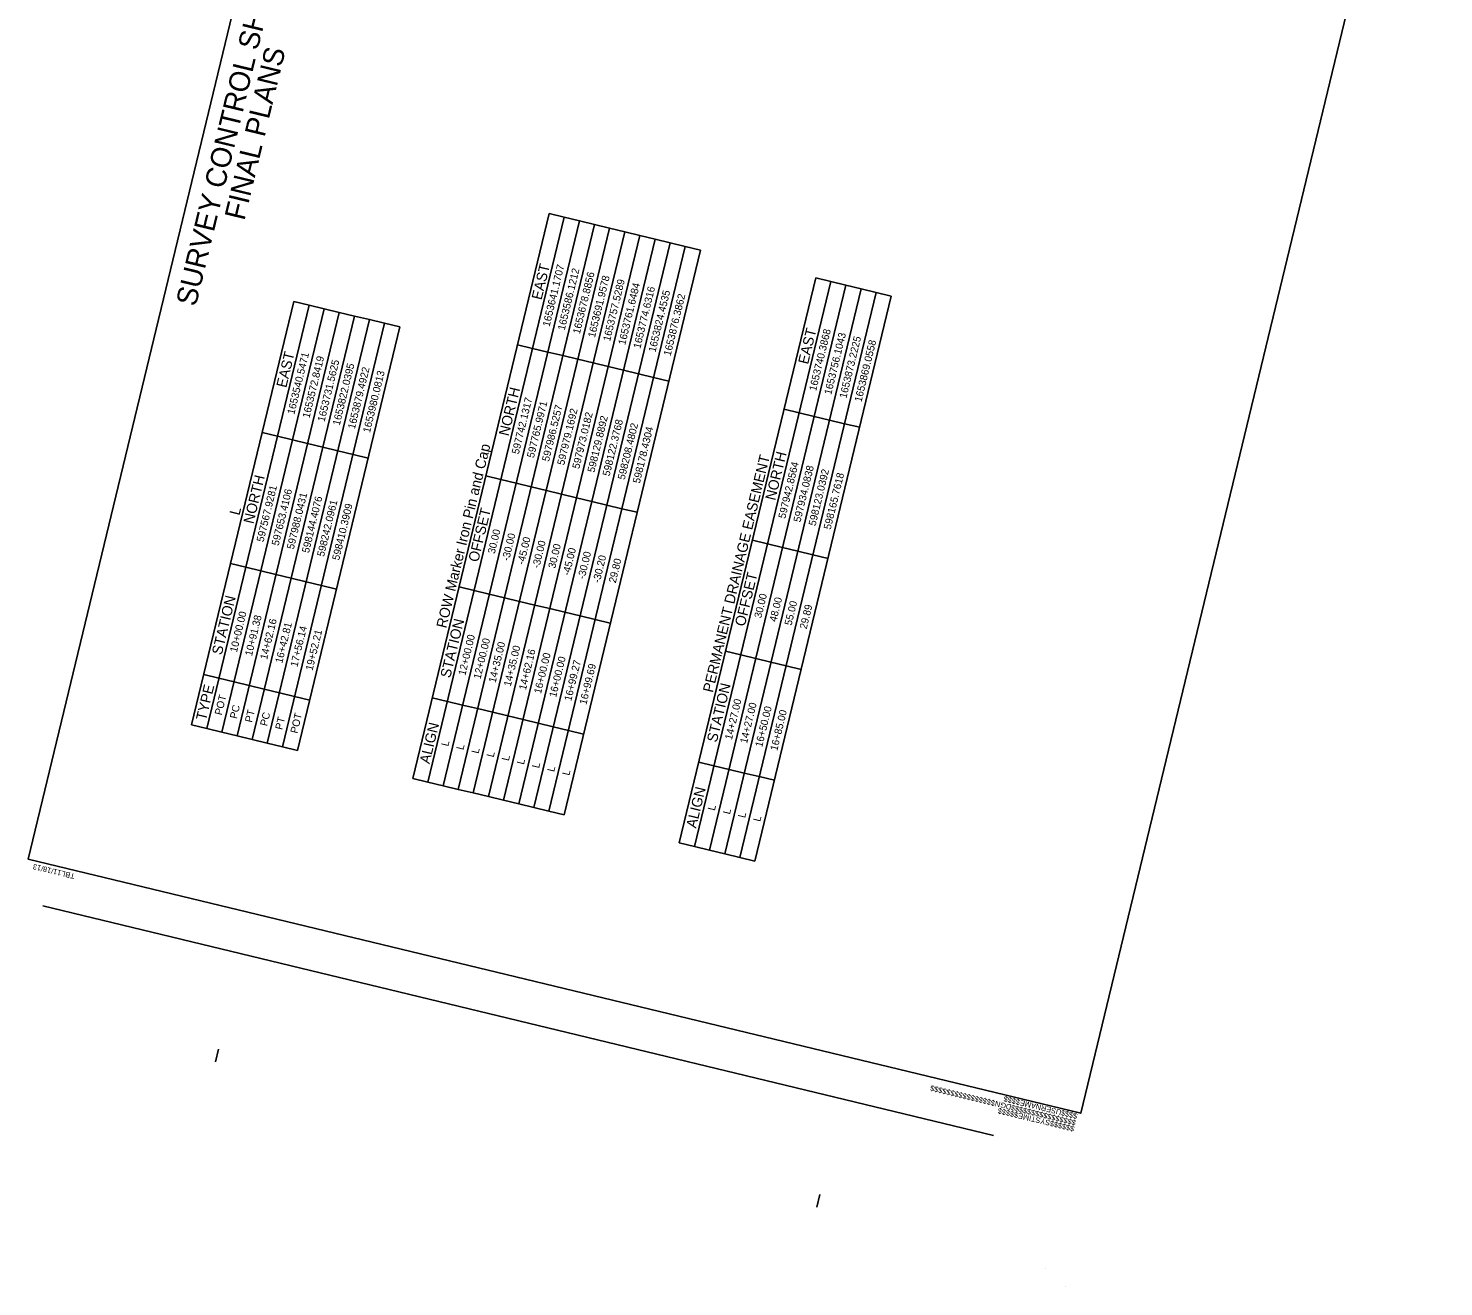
# Model space of a CAD drawing. Extents: x 1649669 to 1659218, y 594717 to 607900.
# Drawn here: x 1649669 to 1659218, y 594717 to 603207 of the extents above; entities that cross this region are included whole.
import ezdxf

# ---------------------------------------------------------------- set-up
doc = ezdxf.new("R2010")
doc.units = 0
for name, color, linetype in [('CTL Sheet Border CELL', 7, 'Continuous'), ('CTL Sheet Notes CELL', 7, 'Continuous'), ('CTL Sheet Table Cell', 7, 'Continuous'), ('CTL Sheet Text', 7, 'Continuous'), ('Sheet Cutting Line CELL', 7, 'Continuous')]:
    doc.layers.add(name, color=color, linetype=linetype)

msp = doc.modelspace()

# ---------------------------------------------------------------- linework, layer by layer
at = {"layer": 'CTL Sheet Border CELL'}
for p, q in [((1650930.7, 596233.5), (1650951.1, 596318)), ((1656768.8, 595886.6), (1656768.8, 595886.6)), ((1656768.8, 595886.6), (1656768.8, 595886.6)), ((1656768.8, 595886.6), (1656768.8, 595886.6)), ((1656768.8, 595886.6), (1656768.8, 595886.6)), ((1656768.8, 595886.6), (1656768.8, 595886.6)), ((1656768.8, 595886.6), (1656768.8, 595886.6)), ((1656768.8, 595886.6), (1656768.8, 595886.6)), ((1656768.8, 595886.6), (1656768.8, 595886.6)), ((1656768.8, 595886.6), (1656768.8, 595886.6)), ((1656768.8, 595886.6), (1656768.8, 595886.6)), ((1656768.8, 595886.6), (1656768.8, 595886.6)), ((1654988, 595253.9), (1655008.4, 595338.4)), ((1656534.7, 594841.1), (1656534.7, 594841.1)), ((1656665.2, 594716.6), (1656665.2, 594716.6))]:
    msp.add_line(p, q, dxfattribs=at)
msp.add_lwpolyline([(1652117.6, 607744.3), (1649668.6, 597600.9), (1656768.8, 595886.6), (1659217.9, 606030)], close=True, dxfattribs=at)
msp.add_lwpolyline([(1656830.1, 596140.2), (1656830.1, 596140.2)], dxfattribs=at)
msp.add_lwpolyline([(1656830.1, 596140.2), (1656830.1, 596140.2)], dxfattribs=at)
at = {"layer": 'CTL Sheet Table Cell'}
for p, q in [((1652262.5, 598146.1), (1653182.5, 601956.6)), ((1652364.6, 598121.4), (1653284.6, 601931.9)), ((1652466.7, 598096.8), (1653386.7, 601907.3)), ((1653182.5, 601956.6), (1653284.6, 601931.9)), ((1653284.6, 601931.9), (1653386.7, 601907.3)), ((1653386.7, 601907.3), (1653488.7, 601882.6)), ((1652568.7, 598072.1), (1653488.7, 601882.6)), ((1652670.8, 598047.5), (1653590.8, 601858)), ((1652772.9, 598022.8), (1653692.9, 601833.4)), ((1652874.9, 597998.2), (1653794.9, 601808.7)), ((1653488.7, 601882.6), (1653590.8, 601858)), ((1653590.8, 601858), (1653692.9, 601833.4)), ((1653692.9, 601833.4), (1653794.9, 601808.7)), ((1653794.9, 601808.7), (1653897, 601784.1)), ((1652977, 597973.6), (1653897, 601784.1)), ((1653079.1, 597948.9), (1653999.1, 601759.4)), ((1653181.1, 597924.3), (1654101.1, 601734.8)), ((1653283.2, 597899.6), (1654203.2, 601710.1)), ((1653897, 601784.1), (1653999.1, 601759.4)), ((1653999.1, 601759.4), (1654101.1, 601734.8)), ((1654101.1, 601734.8), (1654203.2, 601710.1)), ((1654060.8, 597711.9), (1654980.9, 601522.4)), ((1654980.9, 601522.4), (1655082.9, 601497.7)), ((1654162.9, 597687.2), (1655082.9, 601497.7)), ((1654265, 597662.6), (1655185, 601473.1)), ((1654367, 597637.9), (1655287.1, 601448.4)), ((1654469.1, 597613.3), (1655389.1, 601423.8)), ((1655082.9, 601497.7), (1655185, 601473.1)), ((1655185, 601473.1), (1655287.1, 601448.4)), ((1655287.1, 601448.4), (1655389.1, 601423.8)), ((1655389.1, 601423.8), (1655491.2, 601399.2)), ((1650770.4, 598506.3), (1651460.4, 601364.2)), ((1650872.5, 598481.7), (1651562.5, 601339.6)), ((1651460.4, 601364.2), (1651562.5, 601339.6)), ((1651562.5, 601339.6), (1651664.5, 601314.9)), ((1654571.2, 597588.6), (1655491.2, 601399.2)), ((1650974.5, 598457), (1651664.5, 601314.9)), ((1651076.6, 598432.4), (1651766.6, 601290.3)), ((1651178.7, 598407.8), (1651868.7, 601265.6)), ((1651280.7, 598383.1), (1651970.7, 601241)), ((1651664.5, 601314.9), (1651766.6, 601290.3)), ((1651766.6, 601290.3), (1651868.7, 601265.6)), ((1651868.7, 601265.6), (1651970.7, 601241)), ((1651970.7, 601241), (1652072.8, 601216.3)), ((1651382.8, 598358.5), (1652072.8, 601216.3)), ((1651484.9, 598333.8), (1652174.9, 601191.7)), ((1652072.8, 601216.3), (1652174.9, 601191.7)), ((1652969, 601072), (1653071, 601047.3)), ((1653071, 601047.3), (1653173.1, 601022.7)), ((1653173.1, 601022.7), (1653275.2, 600998.1)), ((1653275.2, 600998.1), (1653377.2, 600973.4)), ((1653377.2, 600973.4), (1653479.3, 600948.8)), ((1653479.3, 600948.8), (1653581.4, 600924.1)), ((1653581.4, 600924.1), (1653683.4, 600899.5)), ((1653683.4, 600899.5), (1653785.5, 600874.8)), ((1653785.5, 600874.8), (1653887.6, 600850.2)), ((1653887.6, 600850.2), (1653989.6, 600825.6)), ((1654767.3, 600637.8), (1654869.4, 600613.1)), ((1654869.4, 600613.1), (1654971.4, 600588.5)), ((1654971.4, 600588.5), (1655073.5, 600563.9)), ((1655073.5, 600563.9), (1655175.6, 600539.2)), ((1651246.8, 600479.6), (1651348.9, 600455)), ((1655175.6, 600539.2), (1655277.6, 600514.6)), ((1651348.9, 600455), (1651451, 600430.3)), ((1651451, 600430.3), (1651553, 600405.7)), ((1651553, 600405.7), (1651655.1, 600381)), ((1651655.1, 600381), (1651757.2, 600356.4)), ((1651757.2, 600356.4), (1651859.2, 600331.8)), ((1651859.2, 600331.8), (1651961.3, 600307.1)), ((1652755.4, 600187.4), (1652857.5, 600162.8)), ((1652857.5, 600162.8), (1652959.5, 600138.1)), ((1652959.5, 600138.1), (1653061.6, 600113.5)), ((1653061.6, 600113.5), (1653163.7, 600088.8)), ((1653163.7, 600088.8), (1653265.7, 600064.2)), ((1653265.7, 600064.2), (1653367.8, 600039.5)), ((1653367.8, 600039.5), (1653469.9, 600014.9)), ((1653469.9, 600014.9), (1653571.9, 599990.3)), ((1653571.9, 599990.3), (1653674, 599965.6)), ((1653674, 599965.6), (1653776.1, 599941)), ((1654553.7, 599753.2), (1654655.8, 599728.6)), ((1654655.8, 599728.6), (1654757.9, 599703.9)), ((1654757.9, 599703.9), (1654859.9, 599679.3)), ((1654859.9, 599679.3), (1654962, 599654.6)), ((1654962, 599654.6), (1655064.1, 599630)), ((1651033.3, 599595), (1651135.3, 599570.4)), ((1651135.3, 599570.4), (1651237.4, 599545.8)), ((1651237.4, 599545.8), (1651339.5, 599521.1)), ((1651339.5, 599521.1), (1651441.5, 599496.5)), ((1651441.5, 599496.5), (1651543.6, 599471.8)), ((1651543.6, 599471.8), (1651645.7, 599447.2)), ((1651645.7, 599447.2), (1651747.7, 599422.5)), ((1652574.7, 599438.9), (1652676.7, 599414.3)), ((1652676.7, 599414.3), (1652778.8, 599389.6)), ((1652778.8, 599389.6), (1652880.9, 599365)), ((1652880.9, 599365), (1652982.9, 599340.3)), ((1652982.9, 599340.3), (1653085, 599315.7)), ((1653085, 599315.7), (1653187.1, 599291.1)), ((1653187.1, 599291.1), (1653289.1, 599266.4)), ((1653289.1, 599266.4), (1653391.2, 599241.8)), ((1653391.2, 599241.8), (1653493.3, 599217.1)), ((1653493.3, 599217.1), (1653595.3, 599192.5)), ((1654373, 599004.7), (1654475.1, 598980.1)), ((1654475.1, 598980.1), (1654577.1, 598955.4)), ((1654577.1, 598955.4), (1654679.2, 598930.8)), ((1650852.5, 598846.5), (1650954.6, 598821.9)), ((1654679.2, 598930.8), (1654781.3, 598906.1)), ((1654781.3, 598906.1), (1654883.3, 598881.5)), ((1650954.6, 598821.9), (1651056.7, 598797.3)), ((1651056.7, 598797.3), (1651158.7, 598772.6)), ((1651158.7, 598772.6), (1651260.8, 598748)), ((1651260.8, 598748), (1651362.9, 598723.3)), ((1651362.9, 598723.3), (1651464.9, 598698.7)), ((1651464.9, 598698.7), (1651567, 598674)), ((1652394, 598690.4), (1652496, 598665.8)), ((1652496, 598665.8), (1652598.1, 598641.1)), ((1652598.1, 598641.1), (1652700.2, 598616.5)), ((1652700.2, 598616.5), (1652802.2, 598591.8)), ((1652802.2, 598591.8), (1652904.3, 598567.2)), ((1652904.3, 598567.2), (1653006.4, 598542.6)), ((1650770.4, 598506.3), (1650872.5, 598481.7)), ((1650872.5, 598481.7), (1650974.5, 598457)), ((1650974.5, 598457), (1651076.6, 598432.4)), ((1653006.4, 598542.6), (1653108.4, 598517.9)), ((1653108.4, 598517.9), (1653210.5, 598493.3)), ((1653210.5, 598493.3), (1653312.6, 598468.6)), ((1653312.6, 598468.6), (1653414.6, 598444)), ((1651076.6, 598432.4), (1651178.7, 598407.8)), ((1651178.7, 598407.8), (1651280.7, 598383.1)), ((1651280.7, 598383.1), (1651382.8, 598358.5)), ((1651382.8, 598358.5), (1651484.9, 598333.8)), ((1654192.3, 598256.2), (1654294.3, 598231.6)), ((1654294.3, 598231.6), (1654396.4, 598206.9)), ((1654396.4, 598206.9), (1654498.5, 598182.3)), ((1654498.5, 598182.3), (1654600.5, 598157.7)), ((1652262.5, 598146.1), (1652364.6, 598121.4)), ((1652364.6, 598121.4), (1652466.7, 598096.8)), ((1652466.7, 598096.8), (1652568.7, 598072.1)), ((1654600.5, 598157.7), (1654702.6, 598133)), ((1652568.7, 598072.1), (1652670.8, 598047.5)), ((1652670.8, 598047.5), (1652772.9, 598022.8)), ((1652772.9, 598022.8), (1652874.9, 597998.2)), ((1652874.9, 597998.2), (1652977, 597973.6)), ((1652977, 597973.6), (1653079.1, 597948.9)), ((1653079.1, 597948.9), (1653181.1, 597924.3)), ((1653181.1, 597924.3), (1653283.2, 597899.6)), ((1654060.8, 597711.9), (1654162.9, 597687.2)), ((1654162.9, 597687.2), (1654265, 597662.6)), ((1654265, 597662.6), (1654367, 597637.9)), ((1654367, 597637.9), (1654469.1, 597613.3)), ((1654469.1, 597613.3), (1654571.2, 597588.6))]:
    msp.add_line(p, q, dxfattribs=at)
at = {"layer": 'Sheet Cutting Line CELL'}
msp.add_line((1649765.8, 597285.3), (1656181.4, 595736.3), dxfattribs=at)

# ---------------------------------------------------------------- texts
at = {"layer": 'CTL Sheet Border CELL'}
for s, height, rotation, p in [('SURVEY CONTROL SHEET', 139.13, 76.42607, (1650798.4, 601324.6)), ('FINAL PLANS', 139.13, 76.42607, (1651126.1, 601904.5)), ('TBL11/18/13', 36.522, 166.42607, (1649985.4, 597502)), ('$$$$$$$$$$$$$$$$DGN$$$$$$$$$$$$$$$$', 36.522, 166.42607, (1656740.4, 595838.9)), ('$$$$USERNAME$$$$', 36.522, 166.42607, (1656751, 595883.3)), ('$$$$$$SYSTIME$$$$$', 36.522, 166.42607, (1656730.5, 595797.9))]:
    msp.add_text(s, height=height, rotation=rotation, dxfattribs=at).set_placement(p)
at = {"layer": 'CTL Sheet Notes CELL'}
for s, p in [('EAST', (1653130.9, 601370)), ('EAST', (1654929.3, 600935.8)), ('EAST', (1651408.8, 600777.6)), ('NORTH', (1652909.2, 600451.6)), ('ROW Marker Iron Pin and Cap', (1652488.2, 599155.3)), ('PERMANENT DRAINAGE EASEMENT', (1654286.5, 598721.1)), ('NORTH', (1654707.5, 600017.4)), ('NORTH', (1651187.1, 599859.3)), ('L', (1651093, 599916.9)), ('OFFSET', (1652703.9, 599601.3)), ('OFFSET', (1654502.2, 599167.2)), ('STATION', (1650973.6, 598975.2)), ('STATION', (1652515, 598819.1)), ('TYPE', (1650866.6, 598532.1)), ('STATION', (1654313.4, 598384.9)), ('ALIGN', (1652375.3, 598240.2)), ('ALIGN', (1654173.6, 597806))]:
    msp.add_text(s, height=70, rotation=76.42607, dxfattribs=at).set_placement(p)
at = {"layer": 'CTL Sheet Text'}
for s, p in [('1653641.1707', (1653185.2, 601190.2)), ('1653586.1212', (1653287.3, 601165.5)), ('1653678.8856', (1653389.4, 601140.9)), ('1653691.9578', (1653491.4, 601116.2)), ('1653757.5289', (1653593.5, 601091.6)), ('1653761.6484', (1653695.6, 601066.9)), ('1653774.6316', (1653797.6, 601042.3)), ('1653824.4535', (1653899.7, 601017.7)), ('1653876.3862', (1654001.8, 600993)), ('1653740.3868', (1654983.6, 600756)), ('1653756.1043', (1655085.6, 600731.3)), ('1653873.2225', (1655187.7, 600706.7)), ('1653869.0558', (1655289.8, 600682)), ('1653540.5471', (1651463.1, 600597.8)), ('1653572.8419', (1651565.2, 600573.2)), ('1653731.5625', (1651667.2, 600548.5)), ('1653822.0395', (1651769.3, 600523.9)), ('1653879.4922', (1651871.4, 600499.2)), ('1653980.0813', (1651973.4, 600474.6)), ('597742.1317', (1652977.5, 600329.7)), ('597765.9971', (1653079.6, 600305)), ('597986.5257', (1653181.6, 600280.4)), ('597979.1692', (1653283.7, 600255.8)), ('597973.0182', (1653385.8, 600231.1)), ('598129.8892', (1653487.8, 600206.5)), ('598122.3768', (1653589.9, 600181.8)), ('598208.4802', (1653692, 600157.2)), ('598178.4304', (1653794, 600132.5)), ('597942.8564', (1654775.8, 599895.5)), ('597934.0838', (1654877.9, 599870.8)), ('598123.0392', (1654979.9, 599846.2)), ('598165.7618', (1655082, 599821.6)), ('597567.9281', (1651255.4, 599737.3)), ('597653.4106', (1651357.4, 599712.7)), ('597988.0431', (1651459.5, 599688)), ('598144.4076', (1651561.6, 599663.4)), ('598242.0961', (1651663.6, 599638.7)), ('598410.3909', (1651765.7, 599614.1)), ('30.00', (1652815.3, 599657.8)), ('-30.00', (1652911.5, 599609.1)), ('-45.00', (1653013.6, 599584.4)), ('-30.00', (1653115.6, 599559.8)), ('30.00', (1653223.5, 599559.2)), ('-45.00', (1653319.8, 599510.5)), ('-30.00', (1653421.8, 599485.8)), ('-30.20', (1653523.9, 599461.2)), ('29.80', (1653631.8, 599460.7)), ('30.00', (1654613.6, 599223.6)), ('48.00', (1654715.7, 599199)), ('55.00', (1654817.7, 599174.3)), ('29.89', (1654919.8, 599149.7)), ('10+00.00', (1651075.7, 598993.1)), ('10+91.38', (1651177.7, 598968.5)), ('14+62.16', (1651279.8, 598943.8)), ('16+42.81', (1651381.9, 598919.2)), ('17+56.14', (1651483.9, 598894.5)), ('19+52.21', (1651586, 598869.9)), ('12+00.00', (1652617.1, 598837)), ('12+00.00', (1652719.2, 598812.3)), ('14+35.00', (1652821.2, 598787.7)), ('14+35.00', (1652923.3, 598763.1)), ('14+62.16', (1653025.4, 598738.4)), ('16+00.00', (1653127.4, 598713.8)), ('16+00.00', (1653229.5, 598689.1)), ('16+99.27', (1653331.6, 598664.5)), ('16+99.69', (1653433.6, 598639.8)), ('POT', (1650973.3, 598569.3)), ('14+27.00', (1654415.4, 598402.8)), ('14+27.00', (1654517.5, 598378.1)), ('PC ', (1651075.4, 598544.7)), ('PT ', (1651177.5, 598520)), ('PC ', (1651279.5, 598495.4)), ('PT ', (1651381.6, 598470.7)), ('POT', (1651483.7, 598446.1)), ('16+50.00', (1654619.5, 598353.5)), ('16+85.00', (1654721.6, 598328.9)), ('L', (1652501.8, 598359.3)), ('L', (1652603.8, 598334.7)), ('L', (1652705.9, 598310)), ('L', (1652808, 598285.4)), ('L', (1652910, 598260.8)), ('L', (1653012.1, 598236.1)), ('L', (1653114.2, 598211.5)), ('L', (1653216.2, 598186.8)), ('L', (1653318.3, 598162.2)), ('L', (1654300.1, 597925.1)), ('L', (1654402.2, 597900.5)), ('L', (1654504.2, 597875.9)), ('L', (1654606.3, 597851.2))]:
    msp.add_text(s, height=50, rotation=76.42607, dxfattribs=at).set_placement(p)

doc.saveas('drawing.dxf')
